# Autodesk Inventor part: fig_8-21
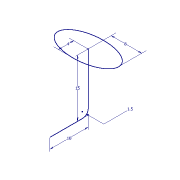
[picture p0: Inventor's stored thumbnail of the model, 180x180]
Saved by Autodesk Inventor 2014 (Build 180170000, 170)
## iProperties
Created: 2013-07
Part Number: fig_8-21
Material: Generic
Document SubType Name: Modeling
Designer: CADCIM
Density: 1 g/cm^3
Appearance: Default
Author: CADCIM
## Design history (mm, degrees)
sketch "Sketch1" dims "d0" = 8, "d1" = 4
  geometry: 2 further points; 1 other entity
  constraints: 1 coincident, 2 other
sketch "Sketch2"
  geometry: L1 (0, 0)-(0, -13.5); L2 (-1.5, -15)-(-10, -15); A1 r 1.5 centre (-1.5, -13.5) between (-1.5, -15) and (0, -13.5); 1 further point
  constraints: 4 end point, 2 point on circle, 2 point on line, 2 tangent, 1 centre point, 1 perpendicular, 1 vertical
  dimensions: "d2" = 15 distance of L1.start point (0, -15); "d3" = 10 distance of point (0, -15) L2.end; "d4" = 1.5 radius of A1
